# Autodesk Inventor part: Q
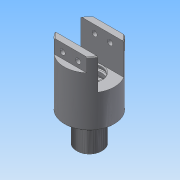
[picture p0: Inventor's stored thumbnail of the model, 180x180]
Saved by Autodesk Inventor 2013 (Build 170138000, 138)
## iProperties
Created: 2019-02
Part Number: Q
Material: 알루미늄 6061
Document SubType Name: Modeling
Designer: Administrator
Density: 2.71 g/cm^3
Mass: 347.17 g
Surface Area: 290.427 cm^2
Volume: 128.107 cm^3
Author: Administrator
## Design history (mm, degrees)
sketch "스케치1"
  geometry: C1 r 29 at (0, 0); 1 further point
  constraints: 1 centre point, 1 coincident
  dimensions: "d0" = 58 diameter of C1
extrude "돌출1" new body sketch "스케치1" distance "d1" = 74; taper "d2" = 0 deg
sketch "스케치2"
  geometry: C1 r 29 at (0, 0) reference; C2 r 13 at (0, 0)
  constraints: 1 centre point, 1 coincident
  dimensions: "d3" = 26 diameter of C2
extrude "돌출2" join sketch "스케치2" distance "d4" = 5; taper "d5" = 0 deg
sketch "스케치3"
  geometry: C1 r 13 at (0, 0) reference; C2 r 15 at (0, 0)
  constraints: 1 centre point, 1 coincident
  dimensions: "d6" = 30 diameter of C2
extrude "돌출3" join sketch "스케치3" distance "d7" = 29; taper "d8" = 0 deg
feature "스레드1" dims "d9" = 10, "d10" = 0
chamfer "모따기1" distance "d11" = 1; stored, may be unused: second distance "d12" = 2, angle "d13" = 45 deg
sketch "스케치5"
  geometry: L1 (29, 74)-(-29, 74) reference; L2 (-29, 1)-(29, 1) reference; L3 (13, -5)-(15, -5) reference; L4 (15, -5)-(15, -34) reference; L5 (15, -34)-(-15, -34) reference; L6 (-15, -34)-(-15, -5) reference; L7 (-15, -5)-(-13, -5) reference; L8 (-13, -5)-(-13, 0) reference; L9 (-13, 0)-(-28, 0) reference; L10 (-28, 0)-(-29, 1) reference; L11 (-29, 1)-(-29, 74) reference; L12 (-29, 74)-(29, 74) reference; L13 (29, 74)-(29, 1) reference; L14 (29, 1)-(28, 0) reference; L15 (28, 0)-(13, 0) reference; L16 (13, 0)-(13, -5) reference; L17 (15, 74)-(-15, 74); L18 (-15, 74)-(-15, 38); L19 (-15, 38)-(15, 38); L20 (15, 38)-(15, 74); 3 further points
  constraints: 8 end point, 3 midpoint, 2 parallel, 1 coincident, 1 horizontal, 1 perpendicular
  dimensions: "d14" = 30 distance of L19.end L18.end; "d15" = 36 distance of L18.end L17.end
extrude "돌출4" cut sketch "스케치5" stored distance "d16" = 29; taper "d17" = 0 deg
sketch "스케치7"
  geometry: C1 r 15 at (0, 0) reference; 1 further point
  constraints: 1 coincident
hole "구멍1" sketch "스케치7" at (0, 0) diameter "d19" = 12.376; stored, may be unused: countersink angle "d23" = 90 deg, drill point angle "d25" = 118 deg; dims "d20" = 18, "d21" = 4, "d22" = 2, "d24" = 22
sketch "스케치10"
  geometry: C1 r 14 at (24.819, 15); A1 r 29 centre (24.819, 15) between (49.639, 0) and (49.639, 30) reference
  constraints: 1 centre point, 1 coincident
  dimensions: "d29" = 28 diameter of C1
extrude "돌출6" cut sketch "스케치10" distance "d30" = 27; taper "d31" = 0 deg
sketch "스케치11"
  geometry: L1 (17, 35.35)-(14, 35.35); L2 (14, 35.35)-(14, 30.65); L3 (14, 30.65)-(17, 30.65); L4 (17, 30.65)-(17, 35.35); L5 (13, -5)-(15, -5) reference; L6 (15, -5)-(15, -34) reference; L7 (15, -34)-(6.188, -34) reference; L8 (6.188, -34)-(6.188, -12) reference; L9 (6.188, -12)-(0, -8.282) reference; L10 (0, -8.282)-(-6.188, -12) reference; L11 (-6.188, -12)-(-6.188, -34) reference; L12 (-6.188, -34)-(-15, -34) reference; L13 (-15, -34)-(-15, -5) reference; L14 (-15, -5)-(-13, -5) reference; L15 (-13, -5)-(-13, 0) reference; L16 (-13, 0)-(-28, 0) reference; L17 (-28, 0)-(-29, 1) reference; L18 (-29, 1)-(-29, 38) reference; L19 (-29, 38)-(-14, 38) reference; L20 (-14, 38)-(-14, 11) reference; L21 (-14, 11)-(14, 11) reference; L22 (14, 11)-(14, 38) reference; L23 (14, 38)-(29, 38) reference; L24 (29, 38)-(29, 1) reference; L25 (29, 1)-(28, 0) reference; L26 (28, 0)-(13, 0) reference; L27 (13, 0)-(13, -5) reference; L28 (13, -5)-(15, -5) reference; L29 (15, -5)-(15, -34) reference; L30 (15, -34)-(6.188, -34) reference; L31 (6.188, -34)-(6.188, -12) reference; L32 (6.188, -12)-(0, -8.282) reference; L33 (0, -8.282)-(-6.188, -12) reference; L34 (-6.188, -12)-(-6.188, -34) reference; L35 (-6.188, -34)-(-15, -34) reference; L36 (-15, -34)-(-15, -5) reference; L37 (-15, -5)-(-13, -5) reference; L38 (-13, -5)-(-13, 0) reference; L39 (-13, 0)-(-28, 0) reference; L40 (-28, 0)-(-29, 1) reference; L41 (-29, 1)-(-29, 38) reference; L42 (-29, 38)-(-14, 38) reference; L43 (-14, 38)-(-14, 11) reference; L44 (-14, 11)-(14, 11) reference; L45 (14, 11)-(14, 38) reference; L46 (14, 38)-(29, 38) reference; L47 (29, 38)-(29, 1) reference; L48 (29, 1)-(28, 0) reference; L49 (28, 0)-(13, 0) reference; L50 (13, 0)-(13, -5) reference; L51 (13, -5)-(15, -5) reference; L52 (15, -5)-(15, -34) reference; L53 (15, -34)-(6.188, -34) reference; L54 (6.188, -34)-(6.188, -12) reference; L55 (6.188, -12)-(0, -8.282) reference; L56 (0, -8.282)-(-6.188, -12) reference; L57 (-6.188, -12)-(-6.188, -34) reference; L58 (-6.188, -34)-(-15, -34) reference; L59 (-15, -34)-(-15, -5) reference; L60 (-15, -5)-(-13, -5) reference; L61 (-13, -5)-(-13, 0) reference; L62 (-13, 0)-(-28, 0) reference; L63 (-28, 0)-(-29, 1) reference; L64 (-29, 1)-(-29, 38) reference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; 2 further points
  constraints: 8 end point, 2 parallel, 1 horizontal, 1 midpoint, 1 perpendicular, 1 point on line
  dimensions: "d32" = 3 distance of L3.end L2.end; "d33" = 4.7 distance of L2.end L1.end; "d34" = 5 distance from line of L23 point (17, 33)
revolve "회전1" sketch "스케치11" stored, may be unused: angle "d35" = 90 deg
sketch "스케치12"
  geometry: L1 (13, -5)-(15, -5) reference; L2 (15, -5)-(15, -34) reference; L3 (15, -34)-(6.188, -34) reference; L4 (6.188, -34)-(6.188, -12) reference; L5 (6.188, -12)-(0, -8.282) reference; L6 (0, -8.282)-(-6.188, -12) reference; L7 (-6.188, -12)-(-6.188, -34) reference; L8 (-6.188, -34)-(-15, -34) reference; L9 (-15, -34)-(-15, -5) reference; L10 (-15, -5)-(-13, -5) reference; L11 (-13, -5)-(-13, 0) reference; L12 (-13, 0)-(-28, 0) reference; L13 (-28, 0)-(-29, 1) reference; L14 (-29, 1)-(-29, 74) reference; L15 (-29, 74)-(-15, 74) reference; L16 (-15, 74)-(-15, 38) reference; L17 (-15, 38)-(-14, 38) reference; L18 (-14, 38)-(-14, 35.35) reference; L19 (-14, 35.35)-(-17, 35.35) reference; L20 (-17, 35.35)-(-17, 30.65) reference; L21 (-17, 30.65)-(-14, 30.65) reference; L22 (-14, 30.65)-(-14, 11) reference; L23 (-14, 11)-(14, 11) reference; L24 (14, 11)-(14, 30.65) reference; L25 (14, 30.65)-(17, 30.65) reference; L26 (17, 30.65)-(17, 35.35) reference; L27 (17, 35.35)-(14, 35.35) reference; L28 (14, 35.35)-(14, 38) reference; L29 (14, 38)-(15, 38) reference; L30 (15, 38)-(15, 74) reference; L31 (15, 74)-(29, 74) reference; L32 (29, 74)-(29, 1) reference; L33 (29, 1)-(28, 0) reference; L34 (28, 0)-(13, 0) reference; L35 (13, 0)-(13, -5) reference; L36 (17, 26.35)-(14, 26.35); L37 (14, 26.35)-(14, 21.65); L38 (14, 21.65)-(17, 21.65); L39 (17, 21.65)-(17, 26.35); L40 (16, 18)-(14, 18); L41 (14, 18)-(14, 11); L42 (14, 11)-(16, 11); L43 (16, 11)-(16, 18); L44 (0, -55.6)-(0, 95.6) reference; 3 further points
  constraints: 16 end point, 4 parallel, 2 horizontal, 2 midpoint, 2 perpendicular, 2 vertical alignment
  dimensions: "d36" = 3 distance of L38.end L37.end; "d37" = 4.7 distance of L37.end L36.end; "d38" = 9 distance of point (17, 24) point (17, 33); "d39" = 2 distance of L23.end L42.end; "d40" = 7 distance of L23.end L40.end
revolve "회전2" sketch "스케치12" stored, may be unused: angle "d41" = 90 deg
sketch "스케치13"
  geometry: C1 r 16 at (0, 0) reference; C2 r 4 at (0, 0)
  constraints: 1 centre point, 1 coincident
  dimensions: "d42" = 8 diameter of C2
extrude "돌출7" cut sketch "스케치13" stored distance "d43" = 27; taper "d44" = 0 deg
fillet "모깎기1" dims "d45" = 0.8
chamfer "모따기2" distance "d46" = 1; stored, may be unused: second distance "d47" = 2, angle "d48" = 45 deg
sketch "스케치14"
  geometry: L1 (-24.819, 15)-(24.819, 15) reference; L2 (-33.797, 22)-(45.283, 22); L3 (45.283, 22)-(45.283, 45.636); L4 (45.283, 45.636)-(-33.797, 45.636); L5 (-33.797, 45.636)-(-33.797, 22)
  constraints: 8 end point, 2 parallel, 1 horizontal, 1 perpendicular
  dimensions: "d49" = 7 distance between parallel lines of L2 L1; "d50" = 23.63573 distance of L4.end L2.start; "d51" = 79.0803 distance of L3.end L4.end
extrude "돌출8" cut sketch "스케치14" distance "d52" = 16; taper "d53" = 0 deg
sketch "스케치15"
  geometry: L1 (24.819, -15)-(-24.819, -15) reference; L2 (-30.704, -37.242)-(36.669, -37.242); L3 (36.669, -37.242)-(36.669, -22); L4 (36.669, -22)-(-30.704, -22); L5 (-30.704, -22)-(-30.704, -37.242)
  constraints: 8 end point, 2 parallel, 1 horizontal, 1 perpendicular
  dimensions: "d54" = 7 distance between parallel lines of L1 L4; "d55" = 15.24173 distance of L4.end L2.start
extrude "돌출9" cut sketch "스케치15" distance "d56" = 16; taper "d57" = 0 deg
sketch "스케치16"
  geometry: L1 (37.789, 0)-(0, 0) reference; C1 r 3 at (27.894, 9); C2 r 3 at (9.894, 9); 1 further point
  constraints: 2 centre point, 1 horizontal alignment
  dimensions: "d58" = 6 diameter of C1; "d59" = 6 diameter of C2; "d60" = 18 distance of C1.centre C2.centre; "d61" = 9 distance from line of C1.centre L1; "d62" = 9 horizontal distance of C2.centre point (18.894, 74)
extrude "돌출10" cut sketch "스케치16" stored distance "d63" = 16; taper "d64" = 0 deg
chamfer "모따기3" distance "d65" = 1; stored, may be unused: second distance "d66" = 2, angle "d67" = 45 deg
chamfer "모따기4" distance "d68" = 1; stored, may be unused: second distance "d69" = 2, angle "d70" = 45 deg
node "작업 평면1"
sketch "스케치17"
  geometry: L1 (5, 45)-(-5, 45); L2 (-5, 45)-(-5, 5); L3 (-5, 5)-(5, 5); L4 (5, 5)-(5, 45); L5 (28, 0)-(-28, 0) reference; 2 further points
  constraints: 8 end point, 2 parallel, 1 horizontal, 1 midpoint, 1 perpendicular, 1 vertical alignment
  dimensions: "d72" = 10 distance of L3.end L2.end; "d73" = 40 distance of L2.end L1.end; "d74" = 5 distance between parallel lines of L5 L3
extrude "돌출11" join sketch "스케치17" stored distance "d75" = 16; taper "d76" = 0 deg
sketch "스케치18"
  geometry: L1 (-5, -45)-(5, -45) reference; L2 (5, -45)-(5, -5) reference; 2 further points
  constraints: 1 other
  dimensions: "d77" = 20 distance from line of L1 point (0, -25); "d78" = 5 distance from line of L2 point (0, -25)
feature "엠보싱1" sketch "스케치18" dims "d79" = 0.5, "d80" = 0
chamfer "모따기5" distance "d81" = 1; stored, may be unused: second distance "d82" = 2, angle "d83" = 45 deg
node "솔리드1"
node "투영된 루프1"
node "절단 모서리 투영1"
node "절단 모서리 투영2"
node "절단 모서리 투영3"
node "절단 모서리 투영4"
node "절단 모서리 투영5"
